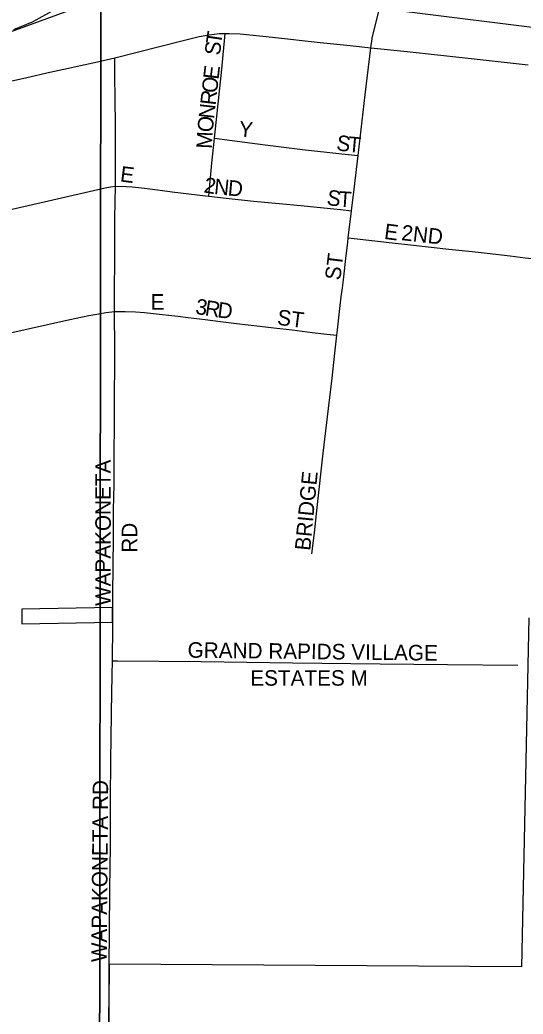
# Model space of a CAD drawing. Extents: x 1443599 to 1910620, y 1028088 to 1361369.
# Drawn here: x 1593811 to 1595433, y 1243124 to 1246329 of the extents above; entities that cross this region are included whole.
import ezdxf

# ---------------------------------------------------------------- set-up
doc = ezdxf.new("R2010")
doc.units = 0
for name, color, linetype in [('GM_X_City_Street', 7, 'Continuous'), ('GM_X_City_Street_Text', 7, 'Continuous'), ('GM_X_Corporation', 7, 'Continuous'), ('GM_X_County_Road', 7, 'Continuous'), ('GM_X_Major_River', 7, 'Continuous'), ('GM_X_Section', 7, 'Continuous'), ('GM_X_State_Route', 7, 'Continuous')]:
    doc.layers.add(name, color=color, linetype=linetype)

msp = doc.modelspace()

# ---------------------------------------------------------------- linework, layer by layer
at = {"layer": 'GM_X_City_Street'}
for points in [[(1594438.4, 1245947.8), (1594460.8, 1246159.8), (1594471, 1246262.1), (1594473.3, 1246285.6)], [(1594901.5, 1245892.1), (1594924.3, 1246087.2), (1594941.7, 1246239.8)], [(1593490.8, 1246066.6), (1593539.4, 1246077.3), (1593590.6, 1246089), (1593740.8, 1246123.6), (1593833.7, 1246144), (1593907.4, 1246160.3), (1593968.3, 1246173.6), (1594006.8, 1246182.1), (1594061.2, 1246194.1), (1594117, 1246206.8)], [(1594420.3, 1245760.9), (1594421.5, 1245774.1), (1594429.9, 1245867), (1594438.4, 1245947.8)], [(1594438.4, 1245947.8), (1594511.1, 1245937.9), (1594601.3, 1245926.5), (1594722.2, 1245912), (1594849.2, 1245897.9), (1594901.5, 1245892.1)], [(1594880.3, 1245714.1), (1594888.7, 1245783.6), (1594901.5, 1245892.1)], [(1594116.3, 1245388.7), (1594116.5, 1245481.5), (1594116.8, 1245531.4), (1594117.4, 1245626), (1594117.7, 1245690.3), (1594119.4, 1245793.4)], [(1594119.4, 1245793.4), (1594153.3, 1245792.2), (1594173, 1245790.7), (1594195, 1245789), (1594221, 1245786), (1594263.3, 1245780.6), (1594302.4, 1245775.5), (1594409.9, 1245762.1), (1594420.3, 1245760.9)], [(1594420.3, 1245760.9), (1594475.7, 1245754.9), (1594563.8, 1245745.3), (1594646.3, 1245737.3), (1594716.9, 1245730.4), (1594769.8, 1245725.2), (1594844.7, 1245717.7), (1594880.3, 1245714.1)], [(1594869.7, 1245626.6), (1594880.3, 1245714.1)], [(1594832.4, 1245312.4), (1594834.4, 1245330.2), (1594843.9, 1245408.2), (1594847, 1245436.8), (1594850.6, 1245465.8), (1594854, 1245491.6), (1594863.2, 1245569.6), (1594867.8, 1245611.7), (1594869.7, 1245626.6)], [(1594869.7, 1245626.6), (1594888.8, 1245624.5), (1594945.2, 1245618.4), (1595001.5, 1245611.8), (1595079.7, 1245603.5), (1595193.7, 1245590.3), (1595268.7, 1245582.4), (1595317.5, 1245577.1), (1595391.5, 1245568.3), (1595440, 1245562.6), (1595483.9, 1245557.4)], [(1593659, 1245294.1), (1593721.6, 1245307.6), (1593838.1, 1245333.3), (1593971.7, 1245362.9), (1594032.9, 1245375.9), (1594065.2, 1245381.6), (1594088.1, 1245385.5), (1594107.1, 1245388), (1594116.3, 1245388.7)], [(1594111.2, 1244434.2), (1594111.3, 1244465.6), (1594111.8, 1244578.7), (1594112.5, 1244648.9), (1594113.4, 1244749.5), (1594115.3, 1244831.5), (1594115.4, 1244920.1), (1594115.8, 1245035), (1594116.1, 1245126.9), (1594116.8, 1245209), (1594117.1, 1245271.4), (1594116.3, 1245386.3), (1594116.3, 1245388.7)], [(1594116.3, 1245388.7), (1594150.2, 1245389.4), (1594183.5, 1245388), (1594212.4, 1245385.6), (1594242.3, 1245382.4), (1594320.7, 1245373.7), (1594353.3, 1245370.3), (1594408.7, 1245363.2), (1594457.5, 1245357.2), (1594509.6, 1245350.4), (1594584.5, 1245341.9), (1594629.4, 1245336.6), (1594688.4, 1245329.6), (1594753.3, 1245321.8), (1594800.7, 1245316.2), (1594832.4, 1245312.4)], [(1594752.2, 1244607.9), (1594760.3, 1244675.3), (1594769.7, 1244756.7), (1594788.7, 1244932.7), (1594805.3, 1245076.2), (1594817.2, 1245173.8), (1594825.9, 1245255.3), (1594832.4, 1245312.4)], [(1594109.2, 1244262.7), (1594111, 1244375.2), (1594111, 1244386.6)], [(1594099.2, 1243285.2), (1594100.2, 1243387), (1594101.6, 1243528.2), (1594103.4, 1243666), (1594103.4, 1243817.1), (1594104.4, 1243941.9), (1594106.5, 1244089.7), (1594106.6, 1244096.6), (1594108.5, 1244218.1), (1594109.2, 1244262.7)], [(1594109.2, 1244262.7), (1594126, 1244262.5), (1594395.7, 1244260.2), (1594689.9, 1244256.2), (1594972.5, 1244253.1), (1595189.1, 1244250.8), (1595416.5, 1244248.3)]]:
    msp.add_lwpolyline(points, dxfattribs=at)
at = {"layer": 'GM_X_Corporation'}
msp.add_lwpolyline([(1593817, 1244429.2), (1593817, 1244382.2), (1594109.9, 1244387.3), (1594109.9, 1244434.3)], close=True, dxfattribs=at)
msp.add_lwpolyline([(1595451.2, 1244401), (1595427.8, 1243275.8), (1594099.2, 1243285.2), (1594075.5, 1240435.4)], dxfattribs=at)
at = {"layer": 'GM_X_County_Road'}
for points in [[(1594111, 1244386.6), (1594111.2, 1244434.2)], [(1594086.3, 1241771.1), (1594087.8, 1241887.3), (1594087.6, 1242018.6), (1594088.2, 1242064.5), (1594089.3, 1242149.9), (1594089.2, 1242245), (1594089.1, 1242340.3), (1594091.2, 1242425.7), (1594094.1, 1242616), (1594094.5, 1242740.7), (1594095.1, 1242868.8), (1594096.9, 1242990.3), (1594097.9, 1243036.2), (1594099.2, 1243256.1), (1594099.2, 1243285.2)]]:
    msp.add_lwpolyline(points, dxfattribs=at)
at = {"layer": 'GM_X_Major_River'}
msp.add_lwpolyline([(1593791.4, 1246298.9), (1593852.4, 1246322.8), (1593926.1, 1246364.2)], dxfattribs=at)
at = {"layer": 'GM_X_Section'}
for points in [[(1597593.9, 1246985.7), (1599490.2, 1246962.2), (1599388.1, 1241707.7), (1594066.4, 1241726.8), (1594072.1, 1246398.5), (1594722.3, 1246399), (1595840.7, 1246258.8), (1596612.1, 1246197.6), (1597158.4, 1246341.7)], [(1588840.9, 1246449.6), (1589265.5, 1246304.1), (1590322.7, 1245979.1), (1590791.1, 1245865.7), (1591140.6, 1245826.7), (1591936.5, 1245793.2), (1592694.2, 1246030.3), (1593579.3, 1246217.5), (1594072.1, 1246398.5), (1594066.4, 1241726.8), (1588782.2, 1241830)]]:
    msp.add_lwpolyline(points, close=True, dxfattribs=at)
at = {"layer": 'GM_X_State_Route'}
for points in [[(1594946.7, 1246271.2), (1594977.6, 1246396.3), (1595032.7, 1246605.4)], [(1594117.3, 1246169.7), (1594117, 1246206.8), (1594332.7, 1246261.8), (1594388.7, 1246276), (1594420.7, 1246281.5), (1594453, 1246285), (1594473.3, 1246285.6), (1594485.5, 1246286), (1594521.2, 1246284.7), (1594625.6, 1246274.2), (1594779, 1246256.8), (1594875.5, 1246246.7), (1594941.7, 1246239.8)], [(1594941.7, 1246239.8), (1594946, 1246268.3), (1594946.7, 1246271.2)], [(1594941.7, 1246239.8), (1595059.8, 1246227.4), (1595265.5, 1246204.6), (1595449.4, 1246184.6)], [(1594119.4, 1245793.4), (1594119.2, 1245854.7), (1594119.7, 1245940.1), (1594119, 1246009), (1594118.4, 1246055), (1594117.3, 1246169.7)], [(1591436.6, 1245186.5), (1591448.2, 1245189.5), (1591541.8, 1245213.9), (1591650.1, 1245241.1), (1591777.7, 1245271.2), (1591910.4, 1245302.4), (1591943.5, 1245310.2), (1592239.3, 1245375.5), (1592466.4, 1245425.7), (1592812.1, 1245502.9), (1593017.7, 1245549.7), (1593017.8, 1245549.7), (1593292.6, 1245610.6), (1593349.7, 1245623.3), (1593400.5, 1245634.1), (1593470.9, 1245649.4), (1593577, 1245672.3), (1593660, 1245691.2), (1593733.7, 1245707.5), (1594085.6, 1245788.3), (1594103.7, 1245791.1), (1594119.4, 1245793.4)]]:
    msp.add_lwpolyline(points, dxfattribs=at)

# ---------------------------------------------------------------- texts
at = {"layer": 'GM_X_City_Street_Text'}
for s, rotation, p in [('T', 81.6111, (1594459.8, 1246248)), ('S', 84.2812, (1594456.4, 1246213.6)), ('E', 83.4003, (1594451.4, 1246135.4)), ('O', 83.4281, (1594446.4, 1246091.7)), ('R', 83.4164, (1594441.8, 1246052.4)), ('N', 83.4281, (1594436.8, 1246008.7)), ('O', 84.0001, (1594432.2, 1245965.1)), ('Y', 354.2916, (1594515.1, 1245953.8)), ('M', 87.4677, (1594429.9, 1245913.1)), ('S', 351.8042, (1594829.1, 1245909.6)), ('T', 354.8459, (1594866.8, 1245904.2)), ('E', 352.8783, (1594132.5, 1245808.6)), ('2', 351.0972, (1594402.1, 1245773.2)), ('N', 354.3401, (1594435.6, 1245768.1)), ('D', 354.6565, (1594479.7, 1245763.7)), ('S', 350.7802, (1594797.7, 1245733.7)), ('T', 356.2552, (1594837.6, 1245727.5)), ('E', 352.6635, (1594983.3, 1245623.5)), ('2ND', 353.6554, (1595038.8, 1245619.4)), ('ST', 82.8783, (1594843.6, 1245488.1)), ('E', 0, (1594232.6, 1245395.1)), ('3', 351.0663, (1594374.8, 1245381.8)), ('R', 351.1325, (1594405.3, 1245377)), ('D', 352.5424, (1594445.8, 1245370.7)), ('ST', 352.8783, (1594638.5, 1245346.6)), ('WAPAKONETA', 90, (1594104.3, 1244439.7)), ('BRIDGE', 84.5067, (1594746.8, 1244616.6)), ('RD', 90, (1594189.4, 1244611.3)), ('GRAND RAPIDS VILLAGE', 359.3098, (1594351.5, 1244273.1)), ('ESTATES M', 0, (1594553.7, 1244182.7)), ('WAPAKONETA RD', 89.5309, (1594091.2, 1243291.2))]:
    msp.add_text(s, height=50, rotation=rotation, dxfattribs=at).set_placement(p)

doc.saveas('drawing.dxf')
